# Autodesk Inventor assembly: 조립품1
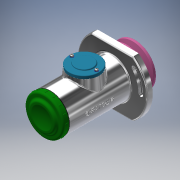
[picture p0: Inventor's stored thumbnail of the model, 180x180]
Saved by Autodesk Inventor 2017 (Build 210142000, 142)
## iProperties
Created: 2022-05
Part Number: 조립품1
Document SubType Name: Assembly
Designer: Administrator
Author: Administrator
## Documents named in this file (22)
- C:\Users\Administrator\Desktop\720506V1007\조립품1.iam
- C:\Users\Administrator\Desktop\720506V1007\본체.ipt
- C:\Users\Administrator\Desktop\720506V1007\개스킷.ipt
- C:\Users\Administrator\Desktop\720506V1007\사이드 커버.ipt
- 사이드 커버.ipt
- C:\Users\Administrator\Desktop\720506V1007\축.ipt
- C:\Users\Administrator\Desktop\720506V1007\키 4 x 4.ipt
- C:\Users\Administrator\Desktop\720506V1007\멈춤링 15 x 1.ipt
- C:\Users\Administrator\Desktop\720506V1007\멈춤링 35 x 1.6.ipt
- C:\Users\Administrator\Desktop\720506V1007\베어링 6202.ipt
- C:\Users\Administrator\Desktop\720506V1007\부시1.ipt
- C:\Users\Administrator\Desktop\720506V1007\부시2.ipt
- C:\Users\Administrator\Desktop\720506V1007\와셔 10 x 21.ipt
- C:\Users\Administrator\Desktop\720506V1007\너트 M10.ipt
- C:\Users\Administrator\Desktop\720506V1007\오일 실 15 x 30 x 7.ipt
- C:\Users\Administrator\Desktop\720506V1007\V-벨트풀리.ipt
- C:\Users\Administrator\Desktop\720506V1007\멈춤나사 M3.ipt
- C:\Users\Administrator\Desktop\720506V1007\와셔 4 x 16.ipt
- C:\Users\Administrator\Desktop\720506V1007\볼트 M4 x 10.ipt
- C:\Users\Administrator\Desktop\720506V1007\탑 커버.ipt
- C:\Users\Administrator\Desktop\720506V1007\와셔 3 x 6.ipt
- C:\Users\Administrator\Desktop\720506V1007\십자볼트 M3 x 10.ipt
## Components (3 placed, 3 different names)
1. 개스킷:1
2. V-벨트풀리:1 — 플러쉬:1
3. ISO 4017 M4 x 10:1
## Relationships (1: Flush 1)
- 플러쉬:1 [Flush]: V-벨트풀리:1
